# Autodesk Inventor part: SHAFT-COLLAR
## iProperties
Created: 2008-03
Part Number: SHAFT-COLLAR
Document SubType Name: Modeling
Density: 1 g/cm^3
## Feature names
1. Extrusion1
2. Hole1
3. Hole2
4. Chamfer1
